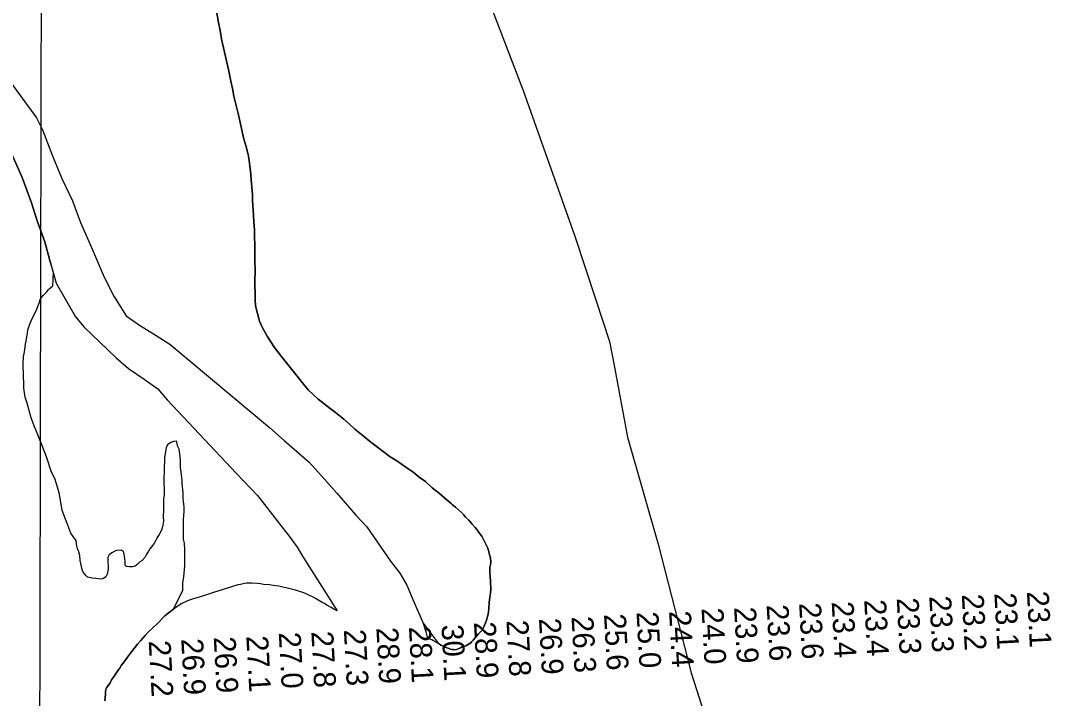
# Model space of a CAD drawing. Extents: x 3192952 to 3230831, y 849296 to 874698.
# Drawn here: x 3207564 to 3210728, y 863734 to 865816 of the extents above; entities that cross this region are included whole.
import ezdxf

# ---------------------------------------------------------------- set-up
doc = ezdxf.new("R2010")
doc.units = 0
for name, color, linetype in [('V-GRID-MAJR', 7, 'Continuous'), ('V-RIVR-RANG', 7, 'Continuous'), ('V-SITE-VEGE', 7, 'Continuous'), ('V-TOPO-BNDY', 7, 'Continuous'), ('V-TOPO-SHOR', 7, 'Continuous')]:
    doc.layers.add(name, color=color, linetype=linetype)

msp = doc.modelspace()

# ---------------------------------------------------------------- linework, layer by layer
at = {"layer": 'V-GRID-MAJR'}
msp.add_spline([(3207605.4, 854713.5), (3207617.8, 860773), (3207630.1, 866835.5), (3207642.5, 872898.1), (3207642.5, 872901.1)], degree=3, dxfattribs=at)
at = {"layer": 'V-SITE-VEGE'}
for p, q in [((3207568.9, 865334), (3207529.2, 865421.4)), ((3207597.2, 865255.9), (3207568.9, 865334)), ((3207615.1, 865201.1), (3207597.2, 865255.9)), ((3207638.5, 865136.3), (3207615.1, 865201.1)), ((3207653.8, 865078.8), (3207638.5, 865136.3)), ((3207664.3, 865041.5), (3207653.8, 865078.8)), ((3207662.9, 865000.9), (3207664.3, 865041.5)), ((3207644.2, 864982.9), (3207648.4, 864988.2)), ((3207648.4, 864988.2), (3207651.5, 864991.3)), ((3207651.5, 864991.3), (3207662.9, 865000.9)), ((3207620.5, 864948.1), (3207623.5, 864958.6)), ((3207623.5, 864958.6), (3207627.6, 864964.9)), ((3207627.6, 864964.9), (3207633.9, 864972.3)), ((3207633.9, 864972.3), (3207644.2, 864982.9)), ((3207599, 864900.8), (3207609.2, 864919.7)), ((3207609.2, 864919.7), (3207613.3, 864929.2)), ((3207613.3, 864929.2), (3207617.4, 864940.7)), ((3207617.4, 864940.7), (3207620.5, 864948.1)), ((3207592.8, 864886), (3207599, 864900.8)), ((3207581.8, 864836.7), (3207584.7, 864856.6)), ((3207584.7, 864856.6), (3207585.7, 864866.1)), ((3207585.7, 864866.1), (3207592.8, 864886)), ((3207578.8, 864822), (3207581.8, 864836.7)), ((3207572.9, 864783.2), (3207575.9, 864797.9)), ((3207575.9, 864797.9), (3207578.8, 864822)), ((3207572, 864762.3), (3207572.9, 864783.2)), ((3207572.4, 864722.5), (3207572, 864762.3)), ((3207573.7, 864701.5), (3207572.4, 864722.5)), ((3207573.8, 864686.9), (3207573.7, 864701.5)), ((3207577.3, 864658.6), (3207573.8, 864686.9)), ((3207583.7, 864640.9), (3207577.3, 864658.6)), ((3207591.3, 864613.7), (3207583.7, 864640.9)), ((3207595.7, 864596), (3207591.3, 864613.7)), ((3207605.3, 864570.9), (3207595.7, 864596)), ((3207612.9, 864553.2), (3207605.3, 864570.9)), ((3207631.1, 864507.3), (3207612.9, 864553.2)), ((3208014.3, 864512.1), (3208010.2, 864503.7)), ((3208024.7, 864519.6), (3208014.3, 864512.1)), ((3208033.1, 864522.8), (3208024.7, 864519.6)), ((3208042.5, 864523.9), (3208033.1, 864522.8)), ((3208043.6, 864521.8), (3208042.5, 864523.9)), ((3208045.8, 864509.3), (3208043.6, 864521.8)), ((3208050.1, 864498.9), (3208045.8, 864509.3)), ((3207642.9, 864476), (3207631.1, 864507.3)), ((3208007.3, 864485.9), (3208005.3, 864472.2)), ((3208010.2, 864503.7), (3208007.3, 864485.9)), ((3208053.4, 864476.9), (3208050.1, 864498.9)), ((3208054.6, 864463.3), (3208053.4, 864476.9)), ((3207659.1, 864429), (3207642.9, 864476)), ((3208005.4, 864458.6), (3208004.5, 864447.1)), ((3208004.5, 864447.1), (3208004.7, 864428.3)), ((3208005.3, 864472.2), (3208005.4, 864458.6)), ((3208054.8, 864443.4), (3208054.6, 864463.3)), ((3207668.7, 864409.2), (3207659.1, 864429)), ((3208004.7, 864428.3), (3208003.8, 864412.5)), ((3208057.1, 864428.8), (3208054.8, 864443.4)), ((3208059.4, 864403.7), (3208057.1, 864428.8)), ((3207677.4, 864382.1), (3207668.7, 864409.2)), ((3207682.8, 864361.2), (3207677.4, 864382.1)), ((3208003.8, 864412.5), (3208004.3, 864359.1)), ((3208059.5, 864394.2), (3208059.4, 864403.7)), ((3208062.9, 864365), (3208059.5, 864394.2)), ((3207691.7, 864311), (3207682.8, 864361.2)), ((3208004.3, 864359.1), (3208002.4, 864346.6)), ((3208063.1, 864347.1), (3208062.9, 864365)), ((3208002.4, 864346.6), (3208002.7, 864312)), ((3208065.4, 864322), (3208063.1, 864347.1)), ((3208065.6, 864307.4), (3208065.4, 864322)), ((3207701.4, 864283.9), (3207691.7, 864311)), ((3208002.7, 864312), (3208001.9, 864291)), ((3208001.9, 864291), (3208002, 864278.5)), ((3208063.7, 864283.3), (3208065.6, 864307.4)), ((3207708.9, 864266.2), (3207701.4, 864283.9)), ((3207717.5, 864241.1), (3207708.9, 864266.2)), ((3207999, 864261.7), (3207996, 864250.1)), ((3208002, 864278.5), (3207999, 864261.7)), ((3208064.3, 864222.5), (3208063.7, 864283.3)), ((3207724.9, 864230.7), (3207717.5, 864241.1)), ((3207734.5, 864218.2), (3207724.9, 864230.7)), ((3207981.6, 864225.9), (3207974.4, 864211.2)), ((3207989.8, 864239.6), (3207981.6, 864225.9)), ((3207996, 864250.1), (3207989.8, 864239.6)), ((3207735.6, 864207.8), (3207734.5, 864218.2)), ((3207738.9, 864193.2), (3207735.6, 864207.8)), ((3207742.2, 864183.8), (3207738.9, 864193.2)), ((3207960.9, 864193.2), (3207956.8, 864185.9)), ((3207968.2, 864203.8), (3207960.9, 864193.2)), ((3207974.4, 864211.2), (3207968.2, 864203.8)), ((3208066.5, 864211), (3208064.3, 864222.5)), ((3208067.8, 864191.2), (3208066.5, 864211)), ((3207745.4, 864172.3), (3207742.2, 864183.8)), ((3207746.6, 864157.6), (3207745.4, 864172.3)), ((3207835.5, 864174.2), (3207831.3, 864166.8)), ((3207831.3, 864166.8), (3207831.5, 864155.3)), ((3207843.8, 864180.6), (3207835.5, 864174.2)), ((3207853.1, 864185.9), (3207843.8, 864180.6)), ((3207859.4, 864188.1), (3207853.1, 864185.9)), ((3207872, 864189.2), (3207859.4, 864188.1)), ((3207878.3, 864186.1), (3207872, 864189.2)), ((3207881.5, 864177.8), (3207878.3, 864186.1)), ((3207882.6, 864170.5), (3207881.5, 864177.8)), ((3207884.9, 864153.8), (3207882.6, 864170.5)), ((3207945.5, 864166.9), (3207936.2, 864156.4)), ((3207949.6, 864174.3), (3207945.5, 864166.9)), ((3207956.8, 864185.9), (3207949.6, 864174.3)), ((3208068.3, 864139.8), (3208067.8, 864191.2)), ((3207753.2, 864129.4), (3207746.6, 864157.6)), ((3207754.3, 864123.1), (3207753.2, 864129.4)), ((3207832.7, 864130.2), (3207829.8, 864115.5)), ((3207831.5, 864155.3), (3207832.7, 864138.6)), ((3207832.7, 864138.6), (3207832.7, 864130.2)), ((3207885, 864146.4), (3207884.9, 864153.8)), ((3207886, 864141.2), (3207885, 864146.4)), ((3207889.2, 864139.1), (3207886, 864141.2)), ((3207897.6, 864138.2), (3207889.2, 864139.1)), ((3207907, 864138.3), (3207897.6, 864138.2)), ((3207915.4, 864139.4), (3207907, 864138.3)), ((3207920.6, 864143.6), (3207915.4, 864139.4)), ((3207928.9, 864152.1), (3207920.6, 864143.6)), ((3207936.2, 864156.4), (3207928.9, 864152.1)), ((3208065.4, 864117.8), (3208067.3, 864130.4)), ((3208067.3, 864130.4), (3208068.3, 864139.8)), ((3207763.8, 864111.7), (3207754.3, 864123.1)), ((3207769.1, 864106.5), (3207763.8, 864111.7)), ((3207783.8, 864102.5), (3207769.1, 864106.5)), ((3207794.3, 864101.5), (3207783.8, 864102.5)), ((3207811.1, 864099.6), (3207794.3, 864101.5)), ((3207818.4, 864101.8), (3207811.1, 864099.6)), ((3207825.6, 864107.1), (3207818.4, 864101.8)), ((3207829.8, 864115.5), (3207825.6, 864107.1)), ((3208061.5, 864087.4), (3208064.4, 864108.4)), ((3208064.4, 864108.4), (3208065.4, 864117.8)), ((3208033.2, 864008.2), (3208061.7, 864066.5)), ((3208061.7, 864066.5), (3208061.5, 864087.4)), ((3208017.2, 863995.3), (3208033.2, 864008.2)), ((3207982.7, 863962.8), (3208006.6, 863987.2)), ((3208006.6, 863987.2), (3208017.2, 863995.3)), ((3207956.8, 863938.4), (3207982.7, 863962.8)), ((3207922.3, 863899.9), (3207931.6, 863910.7)), ((3207931.6, 863910.7), (3207946.2, 863926.9)), ((3207946.2, 863926.9), (3207956.8, 863938.4)), ((3207898.5, 863868.8), (3207904.5, 863876.9)), ((3207904.5, 863876.9), (3207922.3, 863899.9)), ((3207878.7, 863841.8), (3207891.9, 863860.7)), ((3207891.9, 863860.7), (3207898.5, 863868.8)), ((3207856.9, 863811.5), (3207861.5, 863817.6)), ((3207861.5, 863817.6), (3207863.5, 863820.9)), ((3207863.5, 863820.9), (3207868.1, 863827)), ((3207868.1, 863827), (3207872.7, 863834.4)), ((3207872.7, 863834.4), (3207878.7, 863841.8)), ((3207827.8, 863766.3), (3207838.4, 863781.8)), ((3207838.4, 863781.8), (3207843, 863790.6)), ((3207843, 863790.6), (3207848.9, 863798.7)), ((3207848.9, 863798.7), (3207856.9, 863811.5)), ((3207824.6, 863755.5), (3207825.9, 863758.9)), ((3207824.7, 863745.5), (3207824.6, 863755.5)), ((3207825.8, 863762.3), (3207827.8, 863766.3)), ((3207825.9, 863758.9), (3207825.8, 863762.3)), ((3207822.8, 863726.7), (3207824.7, 863745.5))]:
    msp.add_line(p, q, dxfattribs=at)
for points in [[(3209004.3, 864119.6), (3209004.2, 864135), (3209004.8, 864139.7), (3209006.1, 864144.4), (3209007.3, 864152.4), (3209005.9, 864165.2), (3209004.5, 864171.8), (3209002.4, 864178.5), (3209001, 864185.2), (3208996.9, 864197.2), (3208988, 864215.9), (3208979.8, 864231.9), (3208970.9, 864243.2), (3208964.8, 864251.9), (3208958.7, 864258.5), (3208949.9, 864269.1), (3208945.2, 864275.1), (3208939.7, 864281.1), (3208928.9, 864291.7), (3208924.2, 864297.7), (3208917.4, 864305), (3208899.2, 864320.9), (3208889.7, 864328.2), (3208885.6, 864332.8), (3208866, 864348.7), (3208849.8, 864362.6), (3208827.5, 864380.5), (3208806.6, 864399.7), (3208787.7, 864412.9), (3208768.1, 864429.5), (3208760, 864434.8), (3208735.7, 864451.3), (3208718.8, 864463.2), (3208698.6, 864475.7), (3208633.8, 864525.3), (3208615.6, 864539.9), (3208589.9, 864561.1), (3208573, 864575.7), (3208556.1, 864590.9), (3208530.4, 864612.1), (3208514.2, 864624), (3208499.4, 864635.3), (3208477.1, 864653.1), (3208446.7, 864681.6), (3208431.8, 864698.9), (3208416.8, 864718.2), (3208363.2, 864784.7), (3208343.5, 864811.3), (3208332, 864828.6), (3208321.1, 864845.9), (3208305.4, 864873.9), (3208297.2, 864892.6), (3208285.3, 864940), (3208283.8, 864958.1), (3208283.2, 865022.4), (3208283.7, 865039.9), (3208283.2, 865086.8), (3208282.4, 865106.2), (3208281.7, 865171.8), (3208279.4, 865198.6), (3208277.8, 865234.1), (3208276.1, 865262.3), (3208275.3, 865281), (3208271.5, 865326.5), (3208270.6, 865343.9), (3208267, 865369.4), (3208264.9, 865386.1), (3208262, 865404.2), (3208255, 865431.6), (3208249.5, 865451.6), (3208239.7, 865493.1), (3208232.7, 865526.5), (3208218.7, 865584), (3208214.5, 865607.4), (3208208.9, 865630.1), (3208201.8, 865665.6), (3208196.2, 865691.6), (3208189.2, 865718.4), (3208180.8, 865758.5), (3208175.9, 865785.3), (3208171.6, 865810), (3208165.2, 865844.8)], [(3207532.5, 865626.4), (3207612.7, 865516.7), (3207630.5, 865480), (3207662.1, 865399.9), (3207690.2, 865331.1), (3207723.1, 865262.5), (3207747.8, 865195), (3207781.4, 865119), (3207819.9, 865027.5), (3207849.9, 864969.5), (3207887.4, 864908.9), (3207928.5, 864879.9), (3207979.7, 864848.9), (3208021.5, 864821.8), (3208327.6, 864565.5), (3208372.9, 864525.7), (3208449.9, 864459.5), (3208495.3, 864408.3), (3208534.6, 864364.5), (3208592.9, 864296.7), (3208626.1, 864260.2), (3208699.5, 864155), (3208728, 864118.5), (3208749.1, 864081.8), (3208770.4, 864030.4), (3208788.9, 863988.4), (3208799.9, 863964.4), (3208845.4, 863903.1), (3208848.3, 863901.6), (3208853.7, 863897.6), (3208857.1, 863895.7), (3208860.5, 863894.4), (3208864.5, 863893.1), (3208867.9, 863891.1), (3208871.9, 863889.1), (3208875.9, 863887.8), (3208880, 863885.8), (3208883.3, 863885.2), (3208888, 863883.9), (3208892.1, 863884), (3208896.1, 863883.3), (3208901.4, 863884), (3208914.1, 863889.5), (3208919.4, 863891.6), (3208927.5, 863893.7), (3208930.8, 863895.1), (3208945.5, 863903.9), (3208948.1, 863907.3), (3208953.4, 863912.7), (3208969.3, 863931.6), (3208978.6, 863941.1), (3208981.2, 863944.5), (3208991.1, 863965.3), (3208994.4, 863974.1), (3208998.9, 863992.9), (3209000.7, 864008.3), (3209002.5, 864029.1), (3209004.4, 864043.9), (3209005, 864049.9), (3209006.3, 864057.9), (3209006.8, 864067.3), (3209006.6, 864094.1), (3209004.3, 864119.6)]]:
    msp.add_lwpolyline(points, dxfattribs=at)
at = {"layer": 'V-TOPO-BNDY'}
for p, q in [((3208961.2, 865981.9), (3209106.5, 865601.3)), ((3209106.5, 865601.3), (3209264.6, 865153.9)), ((3209264.6, 865153.9), (3209329.6, 864958)), ((3209329.6, 864958), (3209372, 864830.4)), ((3209372, 864830.4), (3209386.6, 864751.4)), ((3209386.6, 864751.4), (3209426.7, 864536.5)), ((3209426.7, 864536.5), (3209521.3, 864207.5)), ((3209521.3, 864207.5), (3209621.7, 863811.9)), ((3209621.7, 863811.9), (3209926, 862866.7))]:
    msp.add_line(p, q, dxfattribs=at)
at = {"layer": 'V-TOPO-SHOR'}
for points in [[(3208165.2, 865844.8), (3208171.6, 865810), (3208175.9, 865785.3), (3208180.8, 865758.5), (3208189.2, 865718.4), (3208196.2, 865691.6), (3208201.8, 865665.6), (3208208.9, 865630.1), (3208214.5, 865607.4), (3208218.7, 865584), (3208232.7, 865526.5), (3208239.7, 865493.1), (3208249.5, 865451.6), (3208255, 865431.6), (3208262, 865404.2), (3208264.9, 865386.1), (3208267, 865369.4), (3208270.6, 865343.9), (3208271.5, 865326.5), (3208275.3, 865281), (3208276.1, 865262.3), (3208277.8, 865234.1), (3208279.4, 865198.6), (3208281.7, 865171.8), (3208282.4, 865106.2), (3208283.2, 865086.8), (3208283.7, 865039.9), (3208283.2, 865022.4), (3208283.8, 864958.1), (3208285.3, 864940), (3208297.2, 864892.6), (3208305.4, 864873.9), (3208321.1, 864845.9), (3208332, 864828.6), (3208343.5, 864811.3), (3208363.2, 864784.7), (3208416.8, 864718.2), (3208431.8, 864698.9), (3208446.7, 864681.6), (3208477.1, 864653.1), (3208499.4, 864635.3), (3208514.2, 864624), (3208530.4, 864612.1), (3208556.1, 864590.9), (3208573, 864575.7), (3208589.9, 864561.1), (3208615.6, 864539.9), (3208633.8, 864525.3), (3208698.6, 864475.7), (3208718.8, 864463.2), (3208735.7, 864451.3), (3208760, 864434.8), (3208768.1, 864429.5), (3208787.7, 864412.9), (3208806.6, 864399.7), (3208827.5, 864380.5), (3208849.8, 864362.6), (3208866, 864348.7), (3208885.6, 864332.8), (3208889.7, 864328.2), (3208899.2, 864320.9), (3208917.4, 864305), (3208924.2, 864297.7), (3208928.9, 864291.7), (3208939.7, 864281.1), (3208945.2, 864275.1), (3208949.9, 864269.1), (3208958.7, 864258.5), (3208964.8, 864251.9), (3208970.9, 864243.2), (3208979.8, 864231.9), (3208988, 864215.9), (3208996.9, 864197.2), (3209001, 864185.2), (3209002.4, 864178.5), (3209004.5, 864171.8), (3209005.9, 864165.2), (3209007.3, 864152.4), (3209006.1, 864144.4), (3209004.8, 864139.7), (3209004.2, 864135), (3209004.3, 864119.6), (3209006.6, 864094.1), (3209006.8, 864067.3), (3209006.3, 864057.9), (3209005, 864049.9), (3209004.4, 864043.9), (3209002.5, 864029.1), (3209000.7, 864008.3)], [(3207532.5, 865626.4), (3207612.7, 865516.7), (3207630.5, 865480), (3207662.1, 865399.9), (3207690.2, 865331.1), (3207723.1, 865262.5), (3207747.8, 865195), (3207781.4, 865119), (3207819.9, 865027.5), (3207849.9, 864969.5), (3207887.4, 864908.9), (3207928.5, 864879.9), (3207979.7, 864848.9), (3208021.5, 864821.8), (3208327.6, 864565.5), (3208372.9, 864525.7), (3208449.9, 864459.5), (3208495.3, 864408.3), (3208534.6, 864364.5), (3208592.9, 864296.7), (3208626.1, 864260.2), (3208699.5, 864155), (3208728, 864118.5), (3208749.1, 864081.8), (3208770.4, 864030.4), (3208788.9, 863988.4), (3208799.9, 863964.4), (3208808.2, 863937.7), (3208810.3, 863926.3), (3208814, 863920)], [(3207529.2, 865421.4), (3207568.9, 865334), (3207597.2, 865255.9), (3207615.1, 865201.1), (3207638.5, 865136.3), (3207653.8, 865078.8), (3207673.3, 865009.3), (3207731.9, 864906.1), (3207758.4, 864874.2), (3207807.1, 864828.4), (3207857.1, 864780), (3207895, 864747.5), (3207943.5, 864713.8), (3207985.4, 864684.1), (3208013.8, 864650.9), (3208226.5, 864424.5), (3208290.8, 864356.7), (3208358.6, 864270.3), (3208387.8, 864231.7), (3208412.3, 864197.8), (3208429.3, 864170.5), (3208535.1, 864002.4)], [(3208535.1, 864002.4), (3208525, 864007.7), (3208516.9, 864012.9), (3208504.1, 864020.2), (3208496.7, 864024.8), (3208489.9, 864028.1), (3208479.2, 864034.7), (3208471.1, 864039.3), (3208462.3, 864044.6), (3208448.8, 864050.5), (3208440.8, 864054.4), (3208433.4, 864058.4), (3208407.8, 864066.1), (3208391.7, 864070.7), (3208368.9, 864075.8), (3208356.8, 864078.4), (3208339.3, 864080.9), (3208327.9, 864082.8), (3208309.8, 864083.9), (3208300.4, 864085.2), (3208289.7, 864087.1), (3208273.6, 864087.6), (3208257.5, 864087.5), (3208246.8, 864086), (3208238.8, 864083.9), (3208230.1, 864082.5), (3208182, 864067.3), (3208159.3, 864059.7), (3208143.9, 864054.8), (3208128.6, 864049.3), (3208104.5, 864043.1), (3208090.5, 864038.2), (3208075.8, 864033.4), (3208056.5, 864023.8), (3208033.2, 864008.2), (3208017.2, 863995.3), (3208006.6, 863987.2), (3207982.7, 863962.8), (3207956.8, 863938.4), (3207946.2, 863926.9), (3207931.6, 863910.7), (3207922.3, 863899.9), (3207904.5, 863876.9), (3207898.5, 863868.8), (3207891.9, 863860.7), (3207878.7, 863841.8), (3207872.7, 863834.4), (3207868.1, 863827), (3207863.5, 863820.9), (3207861.5, 863817.6), (3207858.8, 863814.2), (3207856.9, 863811.5), (3207848.9, 863798.7), (3207843, 863790.6), (3207838.4, 863781.8), (3207827.8, 863766.3), (3207825.8, 863762.3), (3207825.9, 863758.9), (3207824.6, 863755.5), (3207824.7, 863745.5), (3207822.8, 863726.7)], [(3209000.7, 864008.3), (3208998.9, 863992.9), (3208994.4, 863974.1), (3208991.1, 863965.3), (3208981.2, 863944.5), (3208978.6, 863941.1), (3208969.3, 863931.6), (3208953.4, 863912.7), (3208948.1, 863907.3), (3208945.5, 863903.9), (3208930.8, 863895.1), (3208927.5, 863893.7), (3208919.4, 863891.6), (3208914.1, 863889.5), (3208901.4, 863884), (3208896.1, 863883.3), (3208892.1, 863884), (3208888, 863883.9), (3208883.3, 863885.2), (3208880, 863885.8), (3208875.9, 863887.8), (3208871.9, 863889.1), (3208867.9, 863891.1), (3208864.5, 863893.1), (3208860.5, 863894.4), (3208857.1, 863895.7), (3208853.7, 863897.6), (3208848.3, 863901.6), (3208844.3, 863903.6), (3208840.9, 863904.9), (3208830.8, 863910.8), (3208826.1, 863913.5), (3208820.7, 863916.1), (3208814, 863920)]]:
    msp.add_lwpolyline(points, dxfattribs=at)

# ---------------------------------------------------------------- texts
at = {"layer": 'V-RIVR-RANG'}
for s, p in [('23.4', (3210153.3, 864035.9)), ('23.3', (3210253.1, 864041.6)), ('23.3', (3210353, 864047.3)), ('23.2', (3210452.8, 864053)), ('23.1', (3210552.8, 864056.4)), ('23.1', (3210652.6, 864062.1)), ('24.0', (3209653.9, 864010.3)), ('23.9', (3209753.9, 864013.3)), ('23.6', (3209853.7, 864020.6)), ('23.6', (3209953.5, 864026.3)), ('23.4', (3210053.4, 864030.2)), ('27.8', (3209055.1, 863973.1)), ('26.9', (3209154.9, 863979.1)), ('26.3', (3209254.8, 863984.5)), ('25.6', (3209354.5, 863992.1)), ('25.0', (3209454.3, 863998.8)), ('24.4', (3209554.3, 864001.6)), ('27.3', (3208555.9, 863944.5)), ('28.9', (3208655.7, 863950.5)), ('28.1', (3208755.7, 863953.6)), ('30.1', (3208855.5, 863959.3)), ('28.9', (3208955.2, 863967.7)), ('27.2', (3207956.9, 863910.3)), ('26.9', (3208056.7, 863916.3)), ('26.9', (3208156.5, 863922)), ('27.1', (3208256.5, 863925)), ('27.0', (3208356.1, 863936)), ('27.8', (3208456.1, 863938.8))]:
    msp.add_text(s, height=67, rotation=273.1283, dxfattribs=at).set_placement(p)

doc.saveas('drawing.dxf')
